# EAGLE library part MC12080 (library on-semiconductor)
1.1 GHz Prescaler MECL PLL COMPONENTS ÷10/20/40/80 PRESCALER Source: http://motorola.com/sps .. MC12080.pdf
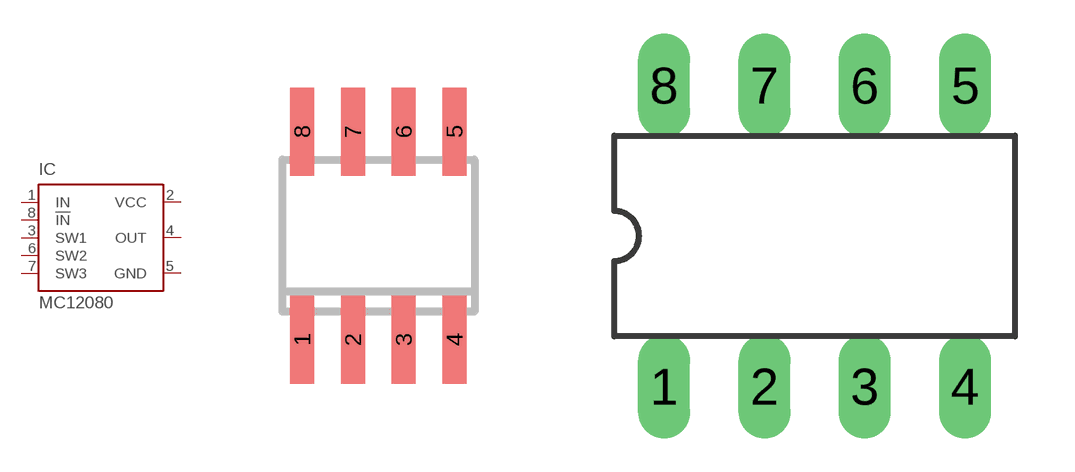
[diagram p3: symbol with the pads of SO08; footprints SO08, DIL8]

Designator prefix IC

## MC12080D (MF: ON SEMICONDUCTOR; MPN: MC12080D; OC_FARNELL: 1607924; OC_NEWARK: 40C2542)  [SO08]
1  IN  in
2  VCC  pwr
3  SW1  in
4  OUT  out
5  GND  pwr
6  SW2  in
7  SW3  in
8  !IN  in

## MC12080P (OC_FARNELL: unknown; OC_NEWARK: unknown)  [DIL8]
Pads as for SO08

## Footprint SO08 (pad centres in mm)
Small Outline Package 8 NS Package M08A
smd 0.6 x 2.2: 1 -1.905,-2.6; 2 -0.635,-2.6; 3 0.635,-2.6; 4 1.905,-2.6; 5 1.905,2.6; 6 0.635,2.6; 7 -0.635,2.6; 8 -1.905,2.6

## Footprint DIL8 (pad centres in mm)
Dual In Line package type P
drill 0.813 long: 1 -3.81,-3.81; 2 -1.27,-3.81; 3 1.27,-3.81; 4 3.81,-3.81; 5 3.81,3.81; 6 1.27,3.81; 7 -1.27,3.81; 8 -3.81,3.81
